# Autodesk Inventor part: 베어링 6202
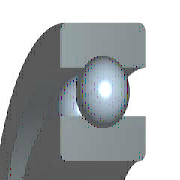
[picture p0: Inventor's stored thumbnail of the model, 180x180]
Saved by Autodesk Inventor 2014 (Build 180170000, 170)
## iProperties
Created: 2015-12
Part Number: 베어링 6202
Material: 강철, 연강
Description: 깊은 그루브 볼 베어링
Document SubType Name: Modeling
Standard: KS B 2023
Designer: mdu
Standards Organization: KS
Language: ko-KR
Size Designation: 6202 - 15 x 35 x 11
Categories: <MemberInstance><Categories><Category DisplayName="샤프트 부품" InternalName="7f7aeb1f-a693-4053-b835-cee3144e0d98" Mnemonic="SHFT"><Category DisplayName="베어링" Inter
Density: 7.86 g/cm^3
Mass: 42.4004 g
Surface Area: 51.5584 cm^2
Volume: 5.39445 cm^3
Appearance: 분홍색
Company: 한국ATC센터
IsCustomPart: 1
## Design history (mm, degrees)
sketch "스케치" dims "d0" = 5.2 (= -0.26 x WD + 0.26 x BD)
  geometry: L1 (2.9, 12.5)-(8.1, 12.5); L2 (5.5, 12.5)-(5.5, 9.9); L3 (5.5, 12.5)-(5.5, 15.1); L4 (3.568, 10.76)-(0, 10.76); L5 (0, 7.5)-(11, 7.5); L6 (3.568, 14.24)-(0, 14.24); L7 (0, 17.5)-(11, 17.5); L8 (11, 7.5)-(11, 10.76); L9 (7.432, 10.76)-(11, 10.76); L10 (7.432, 14.24)-(11, 14.24); L11 (11, 17.5)-(11, 14.24); L12 (-1.4, 0)-(8.4, 0) reference; L13 (0, -0.3)-(0, 5.3) reference
  constraints: 22 end point, 4 point on line, 2 collinear, 2 perpendicular, 2 symmetric about line, 1 midpoint, 1 parallel, 14 other
  dimensions: "d9" = 15 diameter of L5 L12 (= WD); "d11" = 35 diameter of L7 L12 (= BD); "d12" = 11 distance between parallel lines of L8 L13 (= KB); "d13" = 21.52 diameter of L9 L12 (= 0.326 x BD + 0.674 x WD)
revolve "본체" stored, may be unused: angle "d6" = 90 deg
revolve "볼" stored, may be unused: angle "d7" = 90 deg
pattern_circular "IDS_ARRAYBALL[SIMPL:T]" dims angle "d3" = 360 deg
body "Solid1"
fillet "모깎기1" dims "d1" = 0.6 (= KRS)
other parameters: "WD" = 15 [user parameter; used in 5 equation terms], "BD" = 35 [user parameter; used in 5 equation terms], "KB" = 11 [user parameter; used in 1 equation term], "KRS" = 0.6 [user parameter; used in 1 equation term], "d4" = 0, "d5" = 0, "d8" = 0, "d14" = 0, "d15" = 0, "BBA" = 0 [user parameter], "BC0" = 3750000 [user parameter], "BC" = 7800000 [user parameter], "BR" = 17.5 (= 0.5 x BD) [user parameter], "WR" = 7.5 (= 0.5 x WD) [user parameter]
